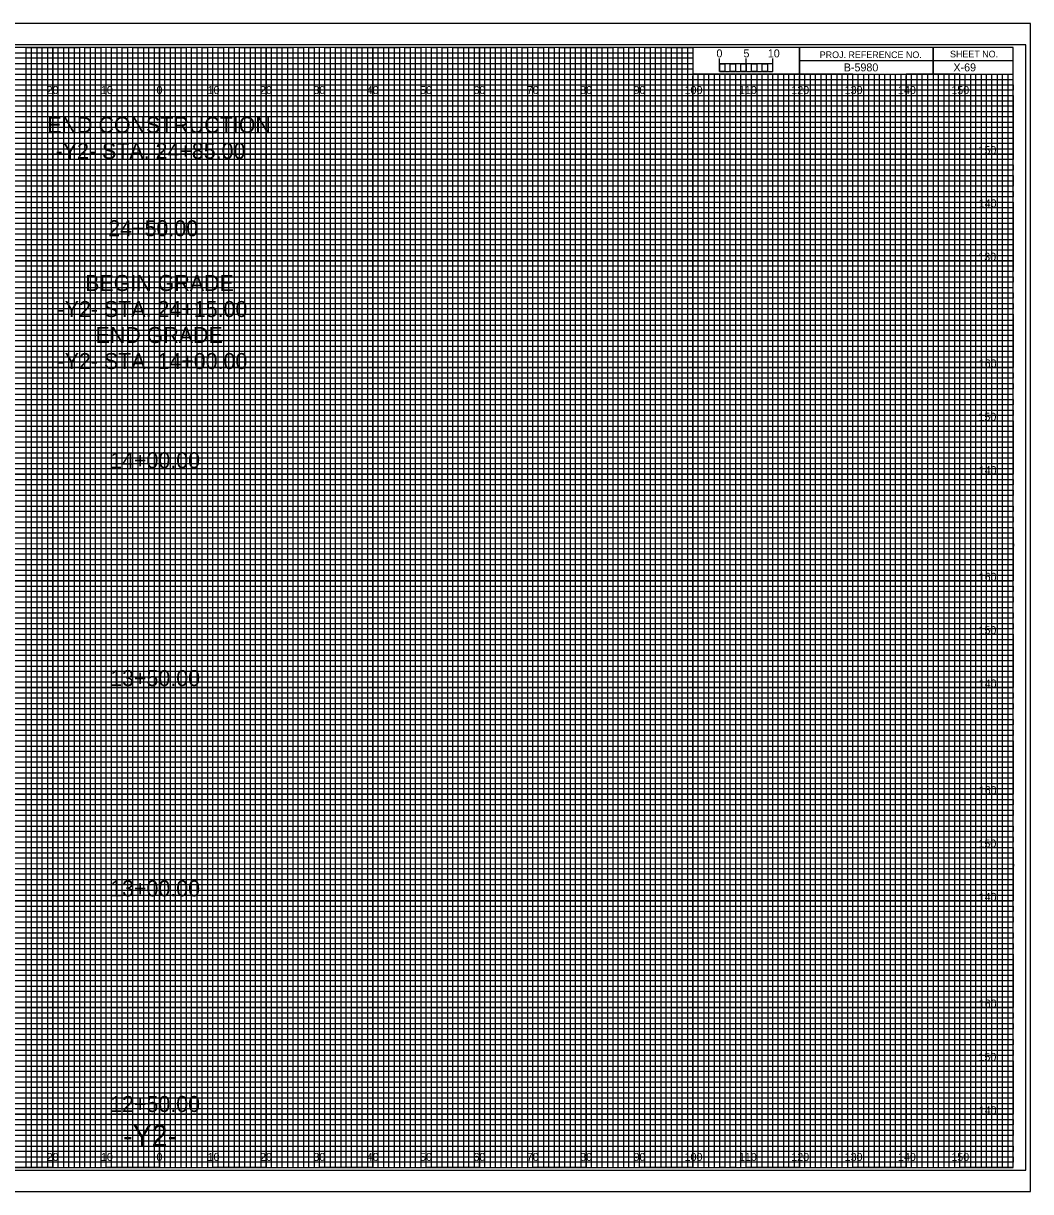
# Model space of a CAD drawing. Extents: x -13 to 323, y -5 to 434.
# Drawn here: x 134.5 to 323.3, y 215.5 to 434.5 of the extents above; entities that cross this region are included whole.
import ezdxf

# ---------------------------------------------------------------- set-up
doc = ezdxf.new("R2010")
doc.units = 0
for name, color, linetype in [('Exist CMT Pavement', 7, 'Continuous'), ('Exist Cross Section Cell', 7, 'Continuous'), ('Exist XS Center Line Elevation Label', 7, 'Continuous'), ('Exist XS Ground Line', 7, 'Continuous'), ('Prop CMT Pvmt Course 1', 7, 'Continuous'), ('Prop CMT Pvmt Course 1 Wedge', 7, 'Continuous'), ('Prop CMT Pvmt Course 2', 7, 'Continuous'), ('Prop CMT Pvmt Course 2 Wedge', 7, 'Continuous'), ('Prop CMT Pvmt Course 3', 7, 'Continuous'), ('Prop CMT Pvmt Course 3 Wedge', 7, 'Continuous'), ('Prop CMT Pvmt Surface', 7, 'Continuous'), ('Prop CMT Pvmt Surface Shoulder', 7, 'Continuous'), ('Prop CMT Shld Paved Course 1', 7, 'Continuous'), ('Prop CMT Shld Paved Course 2', 7, 'Continuous'), ('Prop CMT Shld Paved Course 3', 7, 'Continuous'), ('Prop CMT Slope Grass', 7, 'Continuous'), ('Prop CMT Subgrade Earthwork', 7, 'Continuous')]:
    doc.layers.add(name, color=color, linetype=linetype)

msp = doc.modelspace()

# ---------------------------------------------------------------- linework, layer by layer
at = {"layer": 'Exist XS Center Line Elevation Label'}
for points in [[(125, 220), (135, 220), (135, 430), (145, 430), (145, 220), (155, 220), (155, 430), (165, 430), (165, 220), (175, 220), (175, 430), (185, 430), (185, 220), (195, 220), (195, 430), (205, 430), (205, 220), (215, 220), (215, 430), (225, 430), (225, 220), (235, 220), (235, 430), (245, 430), (245, 220), (255, 220), (255, 430), (259.93, 430), (260, 430), (260, 425), (264.99, 425), (264.99, 220), (275, 220), (275, 425), (285, 425), (285, 220), (295, 220), (295, 425), (305, 425), (305, 220), (315, 220), (315, 425)], [(0, 425), (275, 425)], [(0, 405), (320, 405), (320, 415), (0, 415)], [(0, 385), (320, 385), (320, 395), (0, 395)], [(0, 365), (320, 365), (320, 375), (0, 375)], [(0, 345), (320, 345), (320, 355), (0, 355)], [(0, 325), (320, 325), (320, 335), (0, 335)], [(0, 305), (320, 305), (320, 315), (0, 315)], [(0, 285), (320, 285), (320, 295), (0, 295)], [(0, 265), (320, 265), (320, 275), (0, 275)], [(0, 245), (320, 245), (320, 255), (0, 255)], [(0, 225), (320, 225), (320, 235), (0, 235)]]:
    msp.add_lwpolyline(points, dxfattribs=at)
at = {"layer": 'Exist XS Ground Line'}
for p, q in [((150, 430), (140, 430)), ((140, 430), (140, 220)), ((150, 220), (150, 430)), ((170, 430), (160, 430)), ((160, 430), (160, 220)), ((170, 220), (170, 430)), ((190, 430), (180, 430)), ((180, 430), (180, 220)), ((190, 220), (190, 430)), ((210, 430), (200, 430)), ((200, 430), (200, 220)), ((210, 220), (210, 430)), ((230, 430), (220, 430)), ((220, 430), (220, 220)), ((230, 220), (230, 430)), ((250, 430), (240, 430)), ((240, 430), (240, 220)), ((250, 220), (250, 430)), ((260, 430), (260, 220)), ((270, 220), (270, 425)), ((290, 425), (280, 425)), ((280, 425), (280, 220)), ((290, 220), (290, 425)), ((310, 425), (300, 425)), ((300, 425), (300, 220)), ((310, 220), (310, 425)), ((140, 220), (130, 220)), ((160, 220), (150, 220)), ((180, 220), (170, 220)), ((200, 220), (190, 220)), ((220, 220), (210, 220)), ((240, 220), (230, 220)), ((260, 220), (250, 220)), ((280, 220), (270, 220)), ((300, 220), (290, 220)), ((320, 220), (310, 220)), ((320, 220), (320, 220))]:
    msp.add_line(p, q, dxfattribs=at)
for points in [[(0, 420), (320, 420), (320, 410), (0, 410)], [(0, 400), (320, 400), (320, 390), (0, 390)], [(0, 380), (320, 380), (320, 370), (0, 370)], [(0, 360), (320, 360), (320, 350), (0, 350)], [(0, 340), (320, 340), (320, 330), (0, 330)], [(0, 320), (320, 320), (320, 310), (0, 310)], [(0, 300), (320, 300), (320, 290), (0, 290)], [(0, 280), (320, 280), (320, 270), (0, 270)], [(0, 260), (320, 260), (320, 250), (0, 250)], [(0, 240), (320, 240), (320, 230), (0, 230)]]:
    msp.add_lwpolyline(points, dxfattribs=at)
at = {"layer": 'Prop CMT Pvmt Course 2'}
for p, q in [((265, 425.49), (265, 427.9)), ((265, 426.9), (265, 427.9)), ((270, 425.49), (270, 427.9)), ((275, 425.49), (275, 427.9)), ((275, 426.9), (275, 427.9))]:
    msp.add_line(p, q, dxfattribs=at)
for points in [[(275, 426.9), (265, 426.9), (265, 425.49), (275, 425.49)], [(265, 426.9), (266, 426.9), (266, 425.49), (265, 425.49)], [(267, 426.9), (268, 426.9), (268, 425.49), (267, 425.49)], [(269, 426.9), (270, 426.9), (270, 425.49), (269, 425.49)], [(271, 426.9), (272, 426.9), (272, 425.49), (271, 425.49)], [(273, 426.9), (274, 426.9), (274, 425.49), (273, 425.49)]]:
    msp.add_lwpolyline(points, close=True, dxfattribs=at)
at = {"layer": 'Prop CMT Pvmt Course 3'}
msp.add_lwpolyline([(-13.4, 215.5), (323.3, 215.5), (323.3, 434.5), (-13.4, 434.5)], close=True, dxfattribs=at)
at = {"layer": 'Prop CMT Pvmt Surface'}
for p, q in [((140, 220), (140, 430)), ((150, 220), (150, 430)), ((160, 220), (160, 430)), ((170, 220), (170, 430)), ((180, 220), (180, 430)), ((190, 220), (190, 430)), ((200, 220), (200, 430)), ((210, 220), (210, 430)), ((220, 220), (220, 430)), ((230, 220), (230, 430)), ((240, 220), (240, 430)), ((250, 220), (250, 430)), ((260, 220), (260, 424.69)), ((270, 220), (270, 424.69)), ((280, 220), (280, 424.69)), ((290, 220), (290, 424.69)), ((300, 220), (300, 424.69)), ((310, 220), (310, 424.69)), ((0, 420), (320, 420)), ((0, 410), (320, 410)), ((0, 400), (320, 400)), ((0, 390), (320, 390)), ((0, 380), (320, 380)), ((0, 370), (320, 370)), ((0, 360), (320, 360)), ((0, 350), (320, 350)), ((0, 340), (320, 340)), ((0, 330), (320, 330)), ((0, 320), (320, 320)), ((0, 310), (320, 310)), ((0, 300), (320, 300)), ((0, 290), (320, 290)), ((0, 280), (320, 280)), ((0, 270), (320, 270)), ((0, 260), (320, 260)), ((0, 250), (320, 250)), ((0, 240), (320, 240)), ((0, 230), (320, 230))]:
    msp.add_line(p, q, dxfattribs=at)
at = {"layer": 'Prop CMT Pvmt Surface Shoulder'}
for p, q in [((323.3, 434.5), (-13.4, 434.5)), ((-13.4, 215.5), (323.3, 215.5))]:
    msp.add_line(p, q, dxfattribs=at)
at = {"layer": 'Prop CMT Shld Paved Course 1'}
for p, q in [((0, 429), (260, 429)), ((260, 427.98), (0, 427.98)), ((260, 429), (260, 427.98)), ((0, 427), (260, 427)), ((260, 425.89), (0, 425.89)), ((260, 427), (260, 425.89)), ((0, 424), (320, 424))]:
    msp.add_line(p, q, dxfattribs=at)
for points in [[(0, 423), (270, 423), (320, 423), (320, 422), (0, 422)], [(0, 421), (320, 421), (320, 419), (0, 419)], [(0, 418), (320, 418), (320, 417), (0, 416.98)], [(0, 416), (320, 416), (320, 414), (0, 414)], [(0, 413), (320, 413), (320, 412), (0, 412)], [(0, 411), (320, 411), (320, 409), (0, 409)], [(0, 408), (320, 408), (320, 407), (0, 407)], [(0, 406), (320, 406), (320, 404), (0, 404)], [(0, 403), (320, 403), (320, 402), (0, 402)], [(0, 401), (320, 401), (320, 399), (0, 399)], [(0, 398), (320, 398), (320, 397), (0, 397)], [(0, 396), (320, 396), (320, 393.95), (320, 393), (320, 392), (0, 392)], [(0, 394), (320, 394), (320, 393), (0, 393)], [(0, 391), (320, 391), (320, 389), (0, 389.03)], [(0, 389.03), (320, 389), (320, 388), (0, 388)], [(0, 387), (320, 387), (320, 386), (0, 386)], [(0, 384), (320, 384), (320, 383), (0, 383)], [(0, 382), (320, 382), (320, 381), (0, 381)], [(-0.07, 378.89), (320, 378.89), (320, 377.88), (-0.07, 377.88)], [(0, 377), (320, 377), (320, 376), (0, 376)], [(0, 374), (320, 374), (320, 373), (0, 373)], [(0, 372), (320, 372), (320, 371), (0, 371)], [(0, 369), (320, 369), (320, 368), (0, 368)], [(0, 367), (320, 367), (320, 366), (0, 366)], [(0, 364), (320, 364), (320, 363), (0, 363)], [(0, 362), (320, 362), (320, 361), (0, 361)], [(0, 359), (320, 359), (319.99, 357.98), (0, 358)], [(0, 357), (320, 357), (320, 356), (0, 356)], [(0, 354), (320, 354), (320, 353), (0, 353)], [(0, 352), (320, 352), (320, 351), (0, 351)], [(0, 349), (320, 349), (320, 348), (0, 348)], [(0, 347), (320, 347), (320, 346), (0, 346)], [(0, 344), (320, 344), (320, 343), (0, 343)], [(0, 342), (320, 342), (320, 341), (0, 341)], [(0, 339), (320, 339), (320, 338), (0, 338)], [(0, 336.99), (320.07, 336.91), (320, 336), (0, 336)], [(0, 334), (320, 334), (320, 333), (0, 333)], [(0, 332), (320, 332), (320, 331), (0, 331)], [(0, 329), (320, 329), (320, 328), (0, 328)], [(0, 327), (320, 327), (320, 326), (0, 326)], [(0, 324), (320, 324), (320, 323), (0, 323)], [(0, 322), (320, 322), (320, 321), (0, 321)], [(0, 319), (320, 319), (320, 318), (0, 318)], [(0, 317), (320, 317), (320, 316), (0, 316)], [(0, 314), (320, 314), (320, 313), (0, 313)], [(0, 312), (320, 312), (320, 311), (0, 311)], [(0, 309), (320, 309), (320, 308), (0, 308)], [(0, 307), (320, 307), (320, 306), (0, 306)], [(0, 304), (320, 304), (320, 303), (0, 303)], [(0, 302), (320, 302), (320, 301), (0, 301)], [(0, 299), (320, 299), (319.99, 297.98), (0, 298)], [(0, 297), (320, 297), (320, 296), (0, 296)], [(0, 294), (320, 294), (320, 293), (0, 293)], [(0, 292), (320, 292), (320, 291), (0, 291)], [(0, 289), (320, 289), (320, 288), (0, 288)], [(0, 287), (320, 287), (320, 286), (0, 286)], [(0, 284), (320, 284), (320, 283), (0, 283)], [(0, 282), (320, 282), (320, 281), (0, 281)], [(0, 279), (320, 279), (320, 278), (0, 278)], [(0, 276.99), (320.07, 276.91), (320, 276), (0, 276)], [(0, 274), (320, 274), (320, 273), (0, 273)], [(0, 272), (320, 272), (320, 271), (0, 271)], [(0, 269), (320, 269), (320, 268), (0, 268)], [(0, 267), (320, 267), (320, 266), (0, 266)], [(0, 264), (320, 264), (320, 263), (0, 263)], [(0, 262), (320, 262), (320, 261), (0, 261)], [(0, 259), (320, 259), (320, 258), (0, 258)], [(0, 257), (320, 257), (320, 256), (0, 256)], [(0, 254), (320, 254), (320, 253), (0, 253)], [(0, 252), (320, 252), (320, 251), (0, 251)], [(0, 249), (320, 249), (320, 248), (0, 248)], [(0, 247), (320, 247), (320, 246), (0, 246)], [(0, 244), (320, 244), (320, 243), (0, 243)], [(0, 242), (320, 242), (320, 241), (0, 241)], [(0, 239), (320, 239), (320, 238), (0, 238)], [(0, 237), (320, 237), (320, 236), (0, 236)], [(0, 234), (320, 234), (320, 233), (0, 233)], [(0, 232), (320, 232), (320, 231), (0, 231)], [(0, 229), (320, 229), (320, 228), (0, 228)], [(0, 227), (320, 227), (320, 226), (0, 226)], [(0, 224), (320, 224), (320, 223), (0, 223)], [(0, 222), (320, 222), (320, 221), (0, 221)]]:
    msp.add_lwpolyline(points, dxfattribs=at)
at = {"layer": 'Prop CMT Shld Paved Course 2'}
for p, q in [((305, 430), (305, 425)), ((305, 425), (305, 430)), ((280, 427.5), (280, 425)), ((320, 427.49), (280, 427.49)), ((280, 425), (320, 425))]:
    msp.add_line(p, q, dxfattribs=at)
for points in [[(320, 430), (0, 430), (0, 220), (320, 220)], [(280, 430), (260, 430), (260, 425.03), (280, 425.03)], [(320, 430), (280, 430), (280, 425), (320, 425)]]:
    msp.add_lwpolyline(points, close=True, dxfattribs=at)
at = {"layer": 'Prop CMT Shld Paved Course 3'}
for p, q in [((267, 425), (266.01, 425)), ((266.01, 425), (266.01, 220)), ((267, 220), (267, 425)), ((269, 425), (268, 425)), ((268, 425), (268, 220)), ((269, 220), (269, 425)), ((266.01, 220), (265, 220)), ((268, 220), (267, 220))]:
    msp.add_line(p, q, dxfattribs=at)
for points in [[(135, 220), (136, 220), (136, 430), (137, 430), (137, 220)], [(137, 220), (138, 220), (138, 430), (139, 430), (139, 220)], [(140, 220), (141, 220), (141, 430), (142, 430), (142, 220)], [(142, 220), (143, 220), (143, 430), (144, 430), (144, 220)], [(145, 220), (146, 220), (146, 430), (147, 430), (147, 220)], [(147, 220), (148, 220), (148, 430), (149, 430), (149, 220)], [(150, 220), (151, 220), (151, 430), (152, 430), (152, 220)], [(152, 220), (153, 220), (153, 430), (154, 430), (154, 220)], [(155, 220), (156, 220), (156, 430), (157, 430), (157, 220)], [(157, 220), (158, 220), (158, 430), (159, 430), (159, 220)], [(160, 220), (161, 220), (161, 430), (162, 430), (162, 220)], [(162, 220), (163, 220), (163, 430), (164, 430), (164, 220)], [(165, 220), (166, 220), (166, 430), (167, 430), (167, 220)], [(167, 220), (168, 220), (168, 430), (169, 430), (169, 220)], [(170, 220), (171, 220), (171, 430), (172, 430), (172, 220)], [(172, 220), (173, 220), (173, 430), (174, 430), (174, 220)], [(175, 220), (176, 220), (176, 430), (177, 430), (177, 220)], [(177, 220), (178, 220), (178, 430), (179, 430), (179, 220)], [(180, 220), (181, 220), (181, 430), (182, 430), (182, 220)], [(182, 220), (183, 220), (183, 430), (184, 430), (184, 220)], [(185, 220), (186, 220), (186, 430), (187, 430), (187, 220)], [(187, 220), (188, 220), (188, 430), (189, 430), (189, 220)], [(190, 220), (191, 220), (191, 430), (192, 430), (192, 220)], [(192, 220), (193, 220), (193, 430), (194, 430), (194, 220)], [(195, 220), (196, 220), (196, 430), (197, 430), (197, 220)], [(197, 220), (198, 220), (198, 430), (199, 430), (199, 220)], [(200, 220), (201, 220), (201, 430), (202, 430), (202, 220)], [(202, 220), (203, 220), (203, 430), (204, 430), (204, 220)], [(205, 220), (206, 220), (206, 430), (207, 430), (207, 220)], [(207, 220), (208, 220), (208, 430), (209, 430), (209, 220)], [(210, 220), (211, 220), (211, 430), (212, 430), (212, 220)], [(212, 220), (213, 220), (213, 430), (214, 430), (214, 220)], [(215, 220), (216, 220), (216, 430), (217, 430), (217, 220)], [(217, 220), (218, 220), (218, 430), (219, 430), (219, 220)], [(220, 220), (221, 220), (221, 430), (222, 430), (222, 220)], [(222, 220), (223, 220), (223, 430), (224, 430), (224, 220)], [(225, 220), (226, 220), (226, 430), (227, 430), (227, 220)], [(227, 220), (228, 220), (228, 430), (229, 430), (229, 220)], [(230, 220), (231, 220), (231, 430), (232, 430), (232, 220)], [(232, 220), (233, 220), (233, 430), (234, 430), (234, 220)], [(235, 220), (236, 220), (236, 430), (237, 430), (237, 220)], [(237, 220), (238, 220), (238, 430), (239, 430), (239, 220)], [(240, 220), (241, 220), (241, 430), (242, 430), (242, 220)], [(242, 220), (243, 220), (243, 430), (244, 430), (244, 220)], [(245, 220), (246, 220), (246, 430), (247, 430), (247, 220)], [(247, 220), (248, 220), (248, 430), (249, 430), (249, 220)], [(250, 220), (251, 220), (251, 430), (252, 430), (252, 220)], [(252, 220), (253, 220), (253, 430), (254, 430), (254, 220)], [(255, 220), (256, 220), (256, 430), (257, 430), (257, 220)], [(257, 220), (258, 220), (258, 430), (259, 430), (259, 220)], [(260, 220), (261, 220), (261, 425), (262.02, 425), (262.02, 220)], [(262, 220), (263, 220), (263, 425), (263.99, 425), (263.99, 220)], [(270, 220), (270.98, 220), (270.98, 425), (272, 425), (272, 220)], [(272, 220), (273, 220), (273, 425), (274.05, 425), (274.05, 220)], [(275, 220), (276, 220), (276, 425), (277, 425), (277, 220)], [(277, 220), (278, 220), (278, 425), (279, 425), (279, 220)], [(280, 220), (281, 220), (281, 425), (282, 425), (282, 220)], [(282, 220), (283, 220), (283, 425), (284, 425), (284, 220)], [(285, 220), (286, 220), (286, 425), (287, 425), (287, 220)], [(287, 220), (288, 220), (288, 425), (289, 425), (289, 220)], [(290, 220), (291, 220), (291, 425), (292, 425), (292, 220)], [(292, 220), (293, 220), (293, 425), (294, 425), (294, 220)], [(295, 220), (296, 220), (296, 425), (297, 425), (297, 220)], [(297, 220), (298, 220), (298, 425), (299, 425), (299, 220)], [(300, 220), (301, 220), (301, 425), (302, 425), (302, 220)], [(302, 220), (303, 220), (303, 425), (304, 425), (304, 220)], [(305, 220), (306, 220), (306, 425), (307, 425), (307, 220)], [(307, 220), (308, 220), (308, 425), (309, 425), (309, 220)], [(310, 220), (311, 220), (311, 425), (312, 425), (312, 220)], [(312, 220), (313, 220), (313, 425), (314, 425), (314, 220)], [(315, 220), (316, 220), (316, 425), (317, 425), (317, 220)], [(317, 220), (318, 220), (318, 425), (319, 425), (319, 220)]]:
    msp.add_lwpolyline(points, dxfattribs=at)
at = {"layer": 'Prop CMT Subgrade Earthwork'}
msp.add_lwpolyline([(-10.8, 219.5), (322.4, 219.5), (322.4, 430.5), (-10.8, 430.5)], close=True, dxfattribs=at)

# ---------------------------------------------------------------- texts
at = {"layer": 'Exist CMT Pavement'}
for s, p in [('5', (269.47, 428.12)), ('10', (274.04, 428.12))]:
    msp.add_text(s, height=1.5, dxfattribs=at).set_placement(p)
at = {"layer": 'Exist Cross Section Cell'}
for s, p in [('20', (138.86, 421.25)), ('10', (149.04, 421.25)), ('0', (159.45, 421.25)), ('0', (159.45, 421.25)), ('10', (169.04, 421.25)), ('20', (178.86, 421.25)), ('30', (188.86, 421.25)), ('40', (198.86, 421.25)), ('50', (208.86, 421.25)), ('60', (218.86, 421.25)), ('70', (228.86, 421.25)), ('80', (238.86, 421.25)), ('90', (248.86, 421.25)), ('100', (258.44, 421.25)), ('110', (268.62, 421.25)), ('120', (278.44, 421.25)), ('130', (288.44, 421.25)), ('140', (298.44, 421.25)), ('150', (308.44, 421.25)), ('20', (138.86, 221.25)), ('10', (149.04, 221.25)), ('0', (159.45, 221.25)), ('0', (159.45, 221.25)), ('10', (169.04, 221.25)), ('20', (178.86, 221.25)), ('30', (188.86, 221.25)), ('40', (198.86, 221.25)), ('50', (208.86, 221.25)), ('60', (218.86, 221.25)), ('70', (228.86, 221.25)), ('80', (238.86, 221.25)), ('90', (248.86, 221.25)), ('100', (258.44, 221.25)), ('110', (268.62, 221.25)), ('120', (278.44, 221.25)), ('130', (288.44, 221.25)), ('140', (298.44, 221.25)), ('150', (308.44, 221.25))]:
    msp.add_text(s, height=1.5, dxfattribs=at).set_placement(p)
at = {"layer": 'Prop CMT Pvmt Course 1'}
for s, p in [('150', (313.52, 410)), ('140', (313.57, 400)), ('130', (313.49, 390)), ('160', (313.57, 370)), ('150', (313.52, 360)), ('140', (313.57, 350)), ('160', (313.57, 330)), ('150', (313.52, 320)), ('140', (313.57, 310)), ('160', (313.57, 290)), ('150', (313.52, 280)), ('140', (313.57, 270)), ('160', (313.57, 250)), ('150', (313.52, 240)), ('140', (313.57, 230))]:
    msp.add_text(s, height=1.5, dxfattribs=at).set_placement(p)
at = {"layer": 'Prop CMT Pvmt Course 1 Wedge'}
msp.add_text('X-69', height=1.5, dxfattribs=at).set_placement((308.83, 425.5))
at = {"layer": 'Prop CMT Pvmt Course 2'}
msp.add_text('0', height=1.5, dxfattribs=at).set_placement((264.41, 428.12))
at = {"layer": 'Prop CMT Pvmt Course 2 Wedge'}
msp.add_text('B-5980', height=1.5, dxfattribs=at).set_placement((288.28, 425.5))
at = {"layer": 'Prop CMT Pvmt Course 3 Wedge'}
msp.add_text('-Y2-', height=4, dxfattribs=at).set_placement((153.21, 224))
at = {"layer": 'Prop CMT Shld Paved Course 2'}
for s, p in [('PROJ. REFERENCE NO.', (283.77, 427.99)), ('SHEET NO.', (308.19, 428.12))]:
    msp.add_text(s, height=1.25, dxfattribs=at).set_placement(p)
at = {"layer": 'Prop CMT Slope Grass'}
for s, p in [('END CONSTRUCTION', (138.99, 413.97)), ('-Y2- STA. 24+85.00', (140.55, 409.1)), ('24+50.00', (150.41, 394.59)), ('BEGIN GRADE', (146.08, 384.33)), ('-Y2- STA. 24+15.00', (140.91, 379.45)), ('END GRADE', (148.03, 374.58)), ('-Y2- STA. 14+00.00', (140.91, 369.7)), ('14+00.00', (150.77, 351.1)), ('13+50.00', (150.77, 310.27)), ('13+00.00', (150.77, 270.85)), ('12+50.00', (150.77, 230.43))]:
    msp.add_text(s, height=3, dxfattribs=at).set_placement(p)

doc.saveas('drawing.dxf')
